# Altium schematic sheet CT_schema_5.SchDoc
size 287 x 169 mm
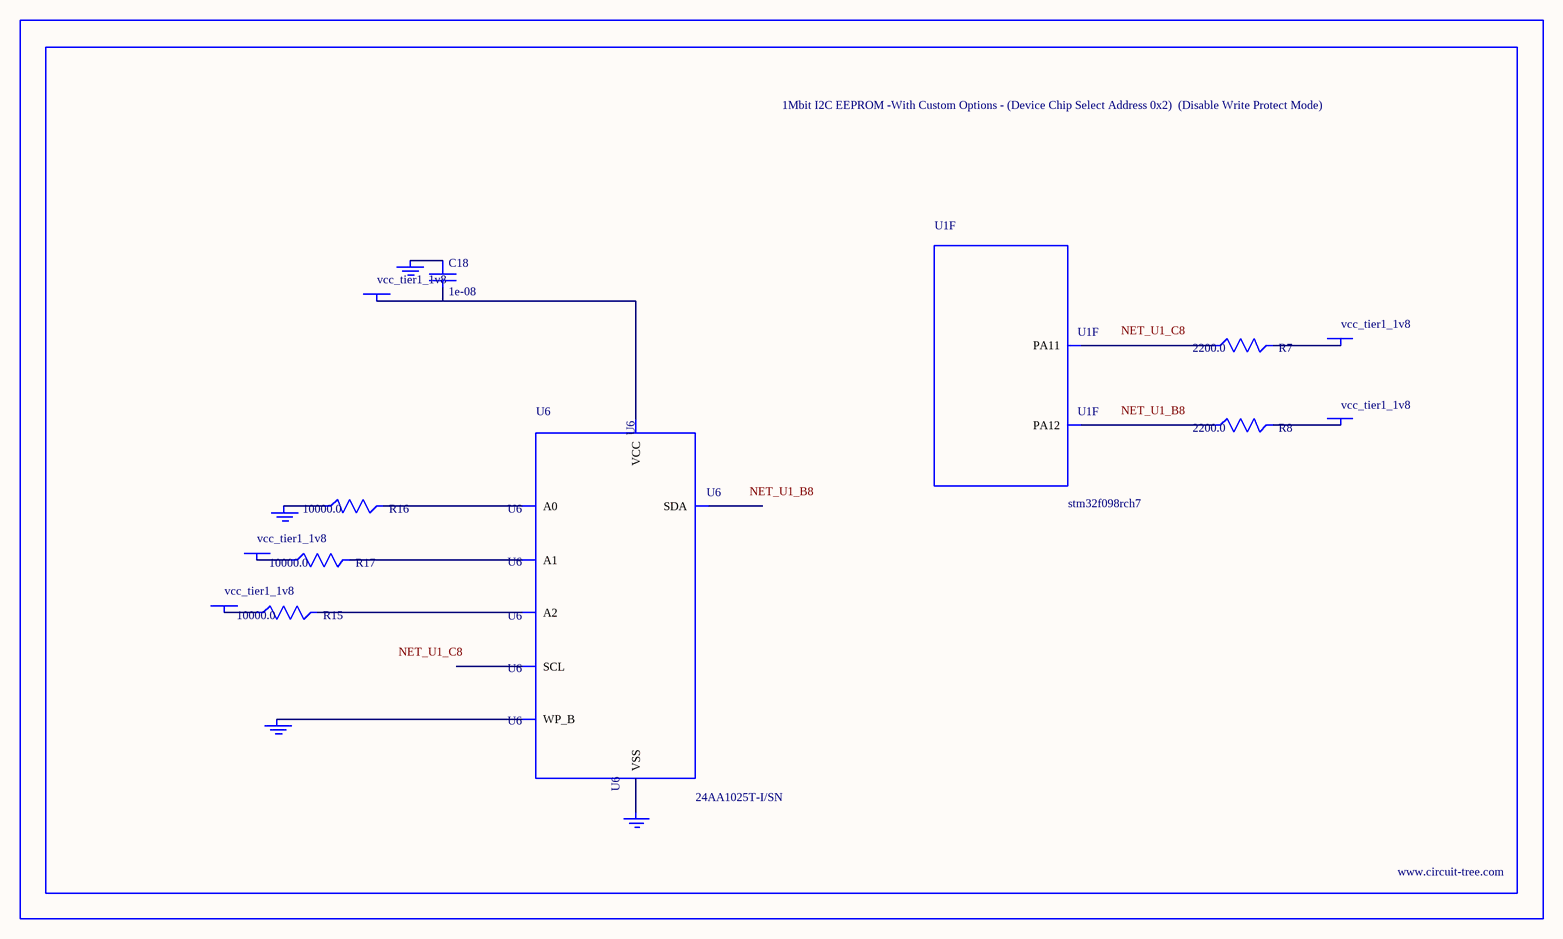
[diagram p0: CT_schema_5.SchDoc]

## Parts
BORDER4  (no value)
C18  1e-08  [C0402]
GND_INSTANCE_4_0  (no value)
GND_INSTANCE_4_1  (no value)
GND_INSTANCE_4_2  (no value)
GND_INSTANCE_4_3  (no value)
POWER_INSTANCE_4_0  vcc_tier1_1v8
POWER_INSTANCE_4_1  vcc_tier1_1v8
POWER_INSTANCE_4_2  vcc_tier1_1v8
POWER_INSTANCE_4_3  vcc_tier1_1v8
POWER_INSTANCE_4_4  vcc_tier1_1v8
R7  2200.0  [R0603]
R8  2200.0  [R0603]
R15  10000.0  [R0603]
R16  10000.0  [R0603]
R17  10000.0  [R0603]
U1  stm32f098rch7  [UFBGA64]  (part F of 6)
U6  24AA1025T-I/SN  [SOIC-8]

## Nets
NetC18_1: C18.1 GND_INSTANCE_4_2.0(GND)
NetC18_2: C18.2 POWER_INSTANCE_4_2.0(PWR) U6.8(VCC)
NetGND_INSTANCE_4_0_0: GND_INSTANCE_4_0.0(GND) R16.1
NetGND_INSTANCE_4_1_0: GND_INSTANCE_4_1.0(GND) U6.7(WP_B)
NetGND_INSTANCE_4_3_0: GND_INSTANCE_4_3.0(GND) U6.4(VSS)
NetPOWER_INSTANCE_4_0_0: POWER_INSTANCE_4_0.0(PWR) R17.1
NetPOWER_INSTANCE_4_1_0: POWER_INSTANCE_4_1.0(PWR) R15.1
NetPOWER_INSTANCE_4_3_0: POWER_INSTANCE_4_3.0(PWR) R7.2
NetPOWER_INSTANCE_4_4_0: POWER_INSTANCE_4_4.0(PWR) R8.2
NetR7_1: R7.1 U1.C8(PA11)
NetR8_1: R8.1 U1.B8(PA12)
NetR15_2: R15.2 U6.3(A2)
NetR16_2: R16.2 U6.1(A0)
NetR17_2: R17.2 U6.2(A1)

Not connected (* = marked no-connect by the designer): U6 5(SDA) 6(SCL)

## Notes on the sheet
- Labels drawn without touching a wire or pin: NET_U1_B8, NET_U1_C8

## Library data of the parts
BORDER4 = BORDER_PAGE4
C18 = C0402C103K3RAC
GND_INSTANCE_4_0-GND_INSTANCE_4_3 = GND
POWER_INSTANCE_4_0-POWER_INSTANCE_4_4 = PWR
R7 R8 = RC0603JR-072K2L
R15-R17 = RC0603JR-0710KL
